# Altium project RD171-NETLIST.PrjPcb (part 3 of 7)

## Sheet 4.SchDoc
size 420 x 297 mm
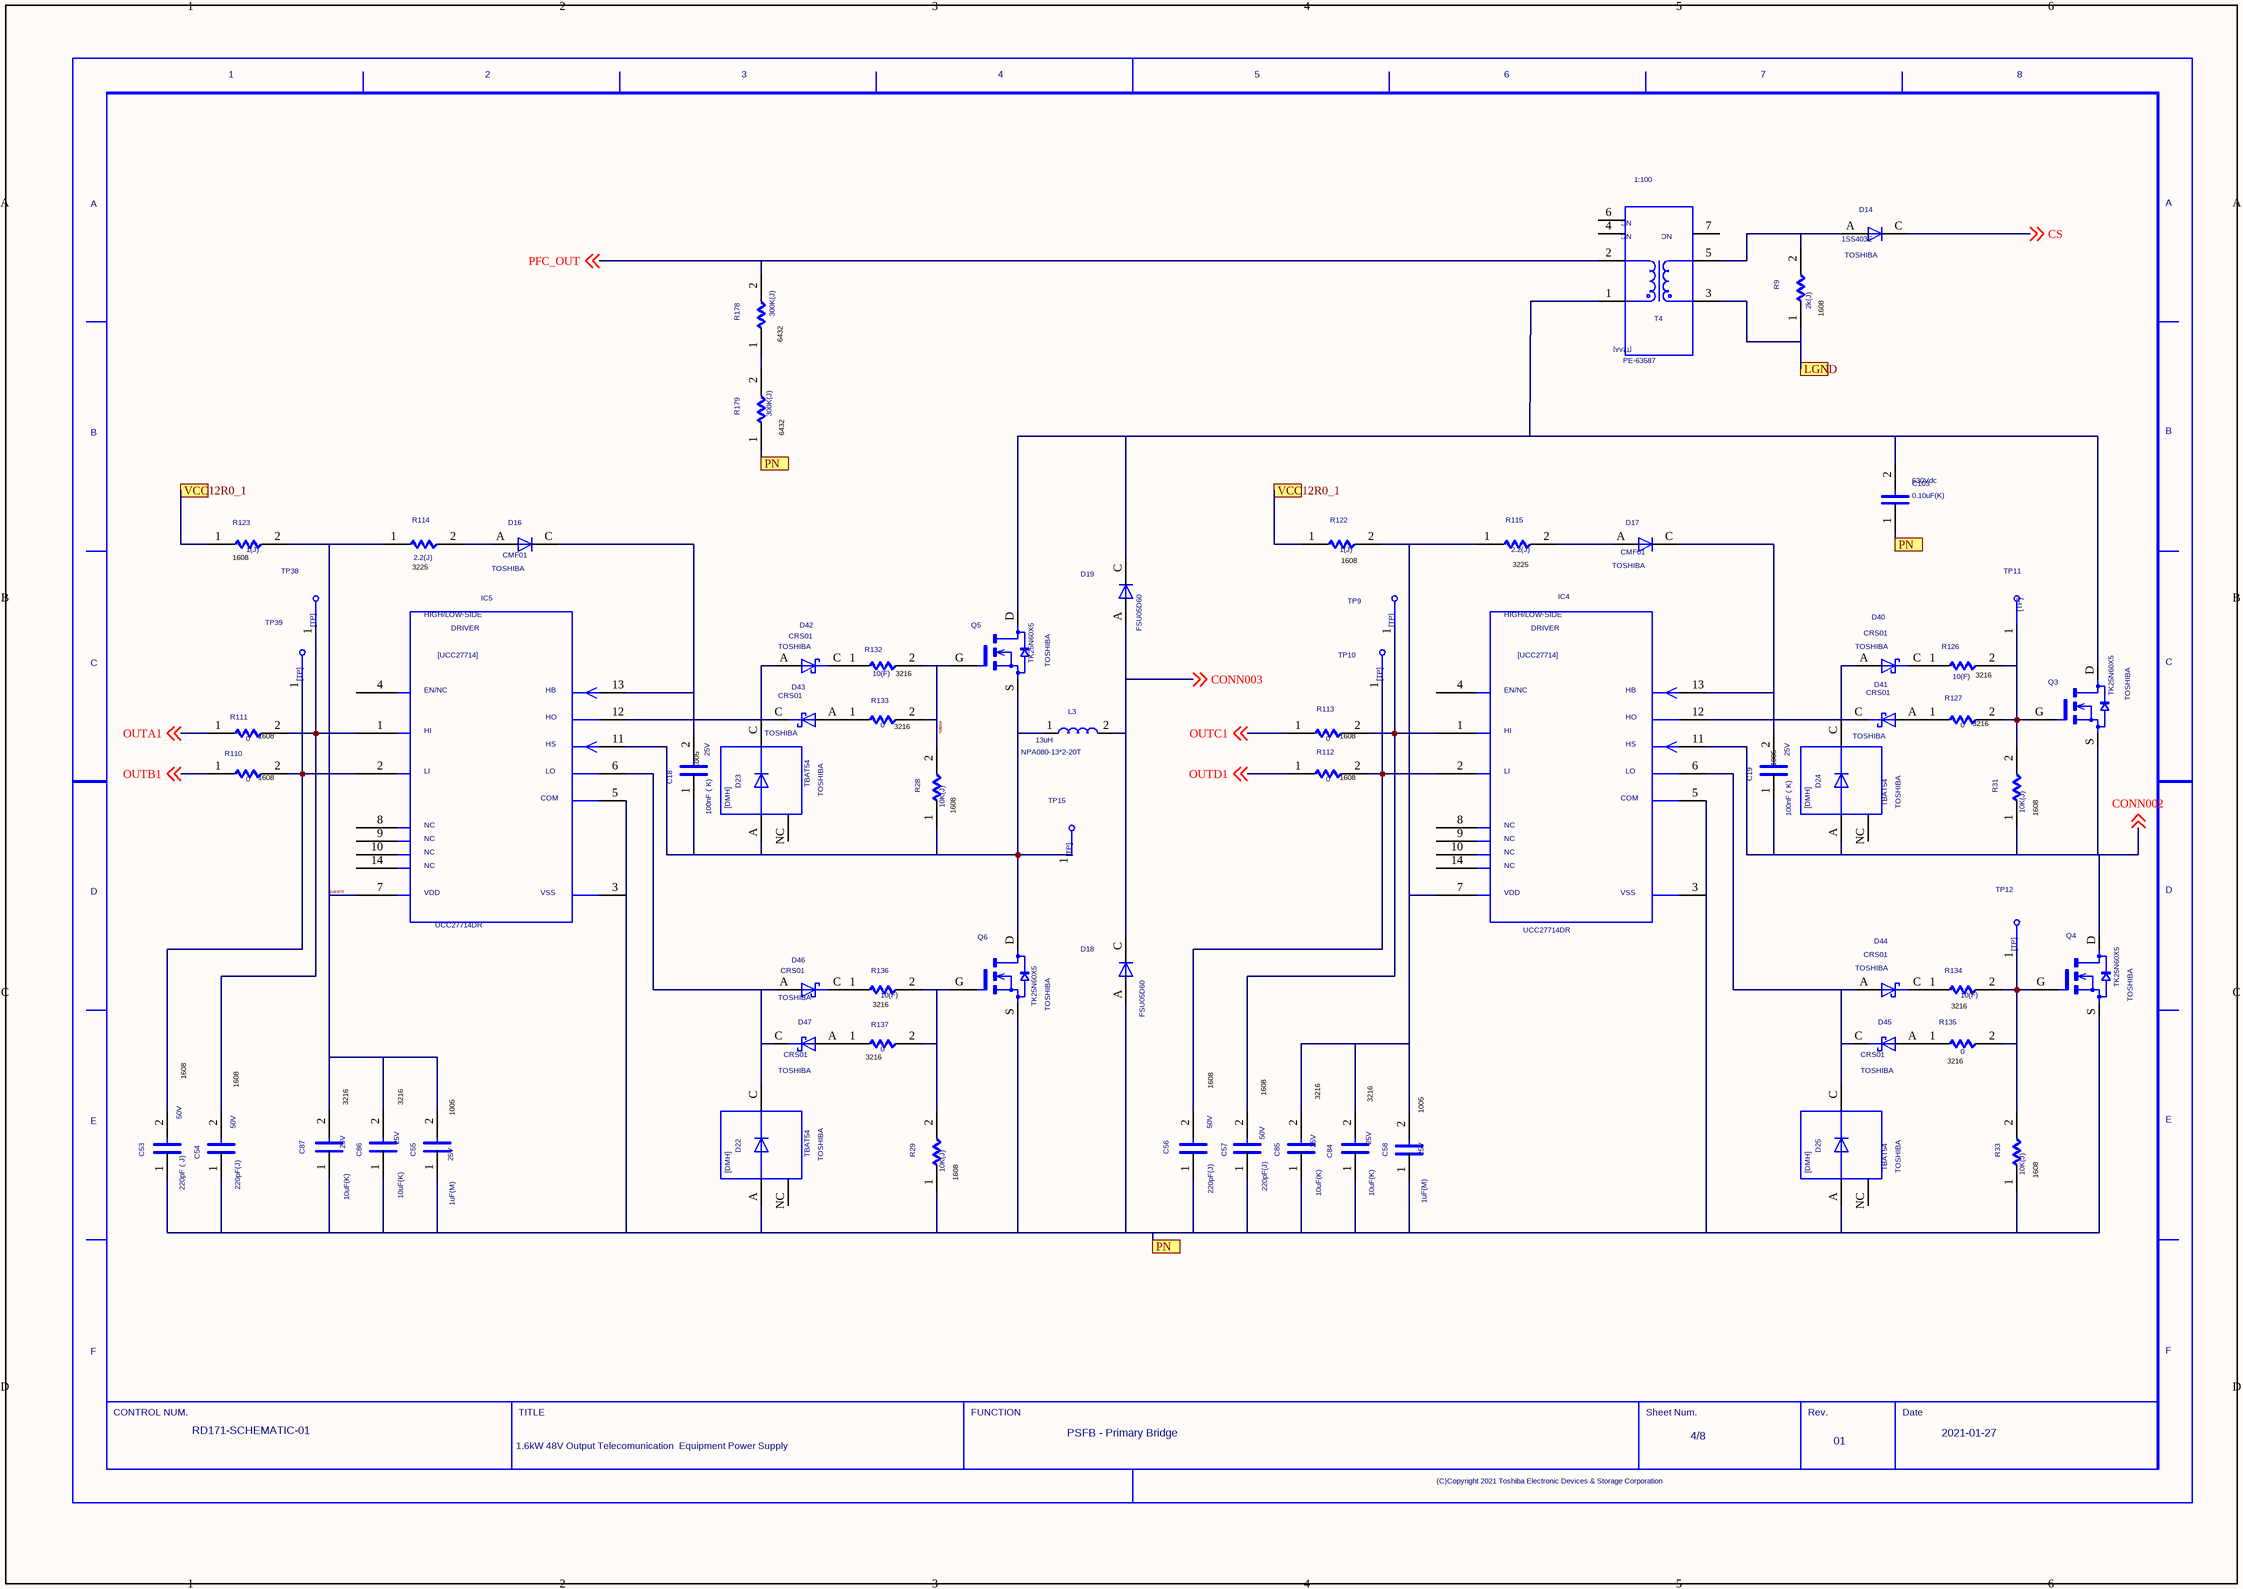
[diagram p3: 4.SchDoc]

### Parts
(Parts that share a designator on the sheet are numbered #1, #2 ... from top to bottom, then left to right.)
C18  VAL2: 25V  VAL1: 100nF（K)  (hidden comment: 100nF)
C19  VAL2: 25V  VAL1: 100nF（K)  (hidden comment: 100nF)
C53  VAL2: 50V  VAL1: 220pF（J)  (hidden comment: 220pF)
C54  VAL2: 50V  VAL1: 220pF(J)  (hidden comment: 220pF)
C55  VAL2: 25V  VAL1: 1uF(M)  (hidden comment: 1uF)
C56  VAL2: 50V  VAL1: 220pF(J)  (hidden comment: 220pF)
C57  VAL2: 50V  VAL1: 220pF(J)  (hidden comment: 220pF)
C58  VAL2: 25V  VAL1: 1uF(M)  (hidden comment: 1uF)
C84  VAL2: 25V  VAL1: 10uF(K)  (hidden comment: 10uF)
C85  VAL2: 25V  VAL1: 10uF(K)  (hidden comment: 10uF)
C86  VAL2: 25V  VAL1: 10uF(K)  (hidden comment: 10uF)
C87  VAL2: 25V  VAL1: 10uF(K)  (hidden comment: 10uF)
C103  VAL1: 0.10uF(K)  VAL2: 630Vdc  (hidden comment: 0.10μF)
D14  USERCOMPTEXT3: TOSHIBA  [1SS403E]  (hidden comment: D14)
D16  USERCOMPTEXT3: TOSHIBA  [CMF01]  (hidden comment: D16)
D17  USERCOMPTEXT3: TOSHIBA  [CMF01]  (hidden comment: D17)
D18  VAL3: FSU05D60  [TRS8E65F]  (hidden comment: D1)
D19  VAL3: FSU05D60  [TRS8E65F]  (hidden comment: D1)
D22  USERCOMPTEXT3: TOSHIBA  [TBAT54]  (hidden comment: D22)
D23  USERCOMPTEXT3: TOSHIBA  [TBAT54]  (hidden comment: D23)
D24  USERCOMPTEXT3: TOSHIBA  [TBAT54]  (hidden comment: D24)
D25  USERCOMPTEXT3: TOSHIBA  [TBAT54]  (hidden comment: D25)
D40  USERCOMPTEXT3: TOSHIBA  [CRS01]  (hidden comment: D40)
D41  USERCOMPTEXT3: TOSHIBA  [CRS01]  (hidden comment: D41)
D42  USERCOMPTEXT3: TOSHIBA  [CRS01]  (hidden comment: D42)
D43  USERCOMPTEXT3: TOSHIBA  [CRS01]  (hidden comment: D43)
D44  USERCOMPTEXT3: TOSHIBA  [CRS01]  (hidden comment: D44)
D45  USERCOMPTEXT3: TOSHIBA  [CRS01]  (hidden comment: D45)
D46  USERCOMPTEXT3: TOSHIBA  [CRS01]  (hidden comment: D46)
D47  USERCOMPTEXT3: TOSHIBA  [CRS01]  (hidden comment: D47)
IC4  IC4  [UCC27714DR]  (value not drawn)
IC5  IC5  [UCC27714DR]  (value not drawn)
L3  VAL3: NPA080-13*2-20T  VAL1: 13uH  [NPA080-14*2-16T]  (hidden comment: 8.4uH)
Q3  USERCOMPTEXT3: TOSHIBA  [TK25N60X5]  (hidden comment: Q3)
Q4  USERCOMPTEXT3: TOSHIBA  [TK25N60X5]  (hidden comment: Q4)
Q5  USERCOMPTEXT3: TOSHIBA  [TK25N60X5]  (hidden comment: Q5)
Q6  USERCOMPTEXT3: TOSHIBA  [TK25N60X5]  (hidden comment: Q6)
R9  VAL1: 2k(J)  (hidden comment: 2k)
R28  VAL1: 10K(J)  (hidden comment: 10k)
R29  VAL1: 10K(J)  (hidden comment: 10k)
R31  VAL1: 10K(J)  (hidden comment: 10k)
R33  VAL1: 10K(J)  (hidden comment: 10k)
R110  0
R111  0
R112  0
R113  0
R114  VAL1: 2.2(J)  (hidden comment: 2.2)
R115  VAL1: 2.2(J)  (hidden comment: 2.2)
R122  VAL1: 1(J)  (hidden comment: 1)
R123  VAL1: 1(J)  (hidden comment: 1)
R126  VAL1: 10(F)  (hidden comment: 10)
R127  0
R132  VAL1: 10(F)  (hidden comment: 10)
R133  0
R134  VAL1: 10(F)  (hidden comment: 10)
R135  0
R136  VAL1: 10(F)  (hidden comment: 10)
R137  0
R178  VAL1: 300K(J)  (hidden comment: 300k)
R179  VAL1: 300K(J)  (hidden comment: 300k)
T4  VAL3: PE-63587  [PE-63587NL]  (hidden comment: 1:100)
TP9  TP9  [HK-2-S]  (value not drawn)
TP10  TP10  [HK-2-S]  (value not drawn)
TP11  TP11  [HK-2-S]  (value not drawn)
TP12  TP12  [HK-2-S]  (value not drawn)
TP15  TP15  [HK-2-S]  (value not drawn)
TP38  TP38  [HK-2-S]  (value not drawn)
TP39  TP39  [HK-2-S]  (value not drawn)
U?#4  DATE: 2021-01-27  REVISION: 01  SHEETNUMBER: 4/8  FUNCTION: PSFB - Primary Bridge  TITLE: 1.6kW 48V Output Telecomunication / Equipment Power Supply  DRAWINGNUMBER: RD171-SCHEMATIC-01  (hidden comment: WAKU_DEF100)

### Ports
LGND, PN, VCC12R0_1

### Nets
CONN002: C19.1 D24.A IC4.11 Q3.S Q4.D R31.1 ; off-sheet CONN002
CONN003: D18.C D19.A L3.2 ; off-sheet CONN003
CS: D14.C ; off-sheet CS
LGND: R9.1 T4.3 ; port LGND
N05004: Q5.G R28.2 R132.2 R133.2
OUTA1: R111.1 ; off-sheet OUTA1
OUTB1: R110.1 ; off-sheet OUTB1
OUTC1: R113.1 ; off-sheet OUTC1
OUTD1: R112.1 ; off-sheet OUTD1
PFC_OUT: R178.2 T4.2 ; off-sheet PFC_OUT
SIG65: C19.2 D17.C IC4.13
SIG75: C18.2 D16.C IC5.13
SIG82: Q6.G R29.2 R136.2 R137.2
SIG89: C54.2 IC5.1 R111.2 TP38.1
SIG90: C53.2 IC5.2 R110.2 TP39.1
SIG91: C58.2 C84.2 C85.2 IC4.7 R115.1 R122.2
SIG92: D17.A R115.2
SIG93: C57.2 IC4.1 R113.2 TP9.1
SIG94: C56.2 IC4.2 R112.2 TP10.1
SIG95: D16.A R114.2
SIG205: Q4.G R33.2 R134.2 R135.2 TP12.1
SIG206: Q3.G R31.2 R126.2 R127.2 TP11.1
SIG249: C18.1 D23.A IC5.11 L3.1 Q5.S Q6.D R28.1 TP15.1
SIGN269: D23.C D42.A D43.C IC5.12
SIGN270: C55.2 C86.2 C87.2 IC5.7 R114.1 R123.2
SIGN271: R178.1 R179.2
SIGN318: D24.C D40.A D41.C IC4.12
SIGN322: D22.C D46.A D47.C IC5.6
SIGN325: D25.C D44.A D45.C IC4.6
SIGN355: C103.2 D19.C Q3.D Q5.D T4.1
SIGN356: D14.A R9.2 T4.5
NetC1_1: C53.1 C54.1 C55.1 C56.1 C57.1 C58.1 C84.1 C85.1 C86.1 C87.1 C103.1 D18.A D22.A D25.A IC4.3 IC4.5 IC5.3 IC5.5 Q4.S Q6.S R29.1 R33.1 R179.1 ; port PN
NetC70_2: R122.1 R123.1 ; port VCC12R0_1
NetD40_C: D40.C R126.1
NetD41_A: D41.A R127.1
NetD42_C: D42.C R132.1
NetD43_A: D43.A R133.1
NetD44_C: D44.C R134.1
NetD45_A: D45.A R135.1
NetD46_C: D46.C R136.1
NetD47_A: D47.A R137.1

Not connected (* = marked no-connect by the designer): D22 NC; D23 NC; D24 NC; D25 NC; IC4 4 8 9 10 14; IC5 4 8 9 10 14; T4 4 6 7

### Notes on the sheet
- (near R9) 1608
- (near R178) 6432
- (near R179) 6432
- (near R123) 1608
- (near R114) 3225
- (near R122) 1608
- (near R115) 3225
- (near R133) 3216
- (near R132) 3216
- (near R127) 3216
- (near R126) 3216
- (near R111) 1608
- (near R110) 1608
- (near C18) 1005
- (near R112) 1608
- (near R113) 1608
- (near C19) 1005
- (near R28) 1608
- (near R31) 1608
- (near R137) 3216
- (near R136) 3216
- (near R135) 3216
- (near R134) 3216
- 1608
- (near C54) 1608
- 3216
- (near C55) 1005
- (near C58) 1005
- (near R29) 1608
- (near R33) 1608

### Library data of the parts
C18 = C: PARTNAME: Chip1005_GS_2; ORIGINALSYMBOLORIGIN: (0,0); TIME: 16:40:04; UPDATEUSER: t5459927; SAVECOUNT: 1; QUADMODEL: CON_220N; FUNCTION: C_C.Normal_package; NOMINALCAPACITA: 220n; RATEDVOLTAGE: 16; CDMASTERCADCELG: KC0005; MAKER: TDK; TEMPCHARACTERI2: B; SIZECODESMD: 1005; OUMEMAKER: TDK ＴＤＫ; ADSCNVFLAG: ON; ADSCOMPONENTNAME: C_1005; COMP: PRT_52; ADSMODELNAME: s_C1005JB1C224KT; FNLEADFREETHET1GT2GMCTH1: N_N_N; VAL3: C1005X7R1E104K050BB; CAPACITANCETOLE: K; OUMECLASSIFICATION: セラミックコンデンサ; OUMEMAKERKATAMEI: C1005JB1C224KT; INSTANCENAME: INS4234
C19 = C: PARTNAME: Chip1005_GS_2; ORIGINALSYMBOLORIGIN: (0,0); TIME: 16:40:04; UPDATEUSER: t5459927; SAVECOUNT: 1; QUADMODEL: CON_220N; FUNCTION: C_C.Normal_package; NOMINALCAPACITA: 220n; RATEDVOLTAGE: 16; CDMASTERCADCELG: KC0005; MAKER: TDK; TEMPCHARACTERI2: B; SIZECODESMD: 1005; OUMEMAKER: TDK ＴＤＫ; COMP: PRT_52; ADSMODELNAME: s_C1005JB1C224KT; FNLEADFREETHET1GT2GMCTH1: N_N_N; VAL3: C1005X7R1E104K050BB; CAPACITANCETOLE: K; OUMECLASSIFICATION: セラミックコンデンサ; OUMEMAKERKATAMEI: C1005JB1C224KT; INSTANCENAME: INS4196
C53 = C: PARTNAME: Chip1608_GS_1; ORIGINALSYMBOLORIGIN: (0,0); TIME: 16:40:04; UPDATEUSER: t5459927; SAVECOUNT: 1; QUADMODEL: CON_220P; FUNCTION: C_C.Normal_package; NOMINALCAPACITA: 220p; RATEDVOLTAGE: 50; CDMASTERCADCELG: KC0008; MAKER: MURATA; SIZECODESMD: 1608; OUMEMAKER: MRT 村田製作所; COMP: PRT_48; ADSMODELNAME: s_GCM1885C1H221JA16D; PMPRODUCTSTYPEG: DME; FNLEADFREETHET1GT2GMCTH1: N_N_N; VAL3: GRM1885C1H221JA01D; CAPACITANCETOLE: J; OUMECLASSIFICATION: セラミックコンデンサ; OUMEMAKERKATAMEI: GCM1885C1H221JA16D; INSTANCENAME: INS4564
C54 = C: PARTNAME: Chip1608_GS_1; ORIGINALSYMBOLORIGIN: (0,0); TIME: 16:40:04; UPDATEUSER: t5459927; SAVECOUNT: 1; QUADMODEL: CON_220P; FUNCTION: C_C.Normal_package; NOMINALCAPACITA: 220p; RATEDVOLTAGE: 50; CDMASTERCADCELG: KC0008; MAKER: MURATA; SIZECODESMD: 1608; OUMEMAKER: MRT 村田製作所; COMP: PRT_48; ADSMODELNAME: s_GCM1885C1H221JA16D; PMPRODUCTSTYPEG: DME; FNLEADFREETHET1GT2GMCTH1: N_N_N; VAL3: GRM1885C1H221JA01D; CAPACITANCETOLE: J; OUMECLASSIFICATION: セラミックコンデンサ; OUMEMAKERKATAMEI: GCM1885C1H221JA16D; INSTANCENAME: INS4576
C55 = C: PARTNAME: Chip1005_GS_2; ORIGINALSYMBOLORIGIN: (0,0); TIME: 16:40:04; UPDATEUSER: t5459927; SAVECOUNT: 1; QUADMODEL: CON_2.2U; FUNCTION: C_C.Normal_package; NOMINALCAPACITA: 2.2u; RATEDVOLTAGE: 10; CDMASTERCADCELG: KC0005; MAKER: TDK; SIZECODESMD: 1005; OUMEMAKER: MRT 村田製作所; ADSCNVFLAG: ON; ADSCOMPONENTNAME: C_1005; COMP: PRT_52; ADSMODELNAME: s_GRM155R61A225KE95D; PMPRODUCTSTYPEG: HD1; FNLEADFREETHET1GT2GMCTH1: N_N_N; VAL3: C1005X5R1E105M050BC; CAPACITANCETOLE: K; OUMECLASSIFICATION: セラミックコンデンサ; OUMEMAKERKATAMEI: GRM155R61A225KE95D; INSTANCENAME: INS4176
C56 = C: PARTNAME: Chip1608_GS_1; ORIGINALSYMBOLORIGIN: (0,0); TIME: 16:40:04; UPDATEUSER: t5459927; SAVECOUNT: 1; QUADMODEL: CON_220P; FUNCTION: C_C.Normal_package; NOMINALCAPACITA: 220p; RATEDVOLTAGE: 50; CDMASTERCADCELG: KC0008; MAKER: MURATA; SIZECODESMD: 1608; OUMEMAKER: MRT 村田製作所; COMP: PRT_48; ADSMODELNAME: s_GCM1885C1H221JA16D; PMPRODUCTSTYPEG: DME; FNLEADFREETHET1GT2GMCTH1: N_N_N; VAL3: GRM1885C1H221JA01D; CAPACITANCETOLE: J; OUMECLASSIFICATION: セラミックコンデンサ; OUMEMAKERKATAMEI: GCM1885C1H221JA16D; INSTANCENAME: INS4452
C57 = C: PARTNAME: Chip1608_GS_1; ORIGINALSYMBOLORIGIN: (0,0); TIME: 16:40:04; UPDATEUSER: t5459927; SAVECOUNT: 1; QUADMODEL: CON_220P; FUNCTION: C_C.Normal_package; NOMINALCAPACITA: 220p; RATEDVOLTAGE: 50; CDMASTERCADCELG: KC0008; MAKER: MURATA; SIZECODESMD: 1608; OUMEMAKER: MRT 村田製作所; COMP: PRT_48; ADSMODELNAME: s_GCM1885C1H221JA16D; PMPRODUCTSTYPEG: DME; FNLEADFREETHET1GT2GMCTH1: N_N_N; VAL3: GRM1885C1H221JA01D; CAPACITANCETOLE: J; OUMECLASSIFICATION: セラミックコンデンサ; OUMEMAKERKATAMEI: GCM1885C1H221JA16D; INSTANCENAME: INS4440
C58 = C: PARTNAME: Chip1005_GS_2; ORIGINALSYMBOLORIGIN: (0,0); TIME: 16:40:04; UPDATEUSER: t5459927; SAVECOUNT: 1; QUADMODEL: CON_2.2U; FUNCTION: C_C.Normal_package; NOMINALCAPACITA: 2.2u; RATEDVOLTAGE: 10; CDMASTERCADCELG: KC0005; MAKER: TDK; SIZECODESMD: 1005; OUMEMAKER: MRT 村田製作所; COMP: PRT_52; ADSMODELNAME: s_GRM155R61A225KE95D; PMPRODUCTSTYPEG: HD1; FNLEADFREETHET1GT2GMCTH1: N_N_N; VAL3: C1005X5R1E105M050BC; CAPACITANCETOLE: K; OUMECLASSIFICATION: セラミックコンデンサ; OUMEMAKERKATAMEI: GRM155R61A225KE95D; INSTANCENAME: INS4186
C84 = C: PARTNAME: Chip3216_GS_1; ORIGINALSYMBOLORIGIN: (0,0); TIME: 16:40:04; UPDATEUSER: t5459927; SAVECOUNT: 1; QUADMODEL: CON_10U; FUNCTION: C_C.Normal_package; NOMINALCAPACITA: 10u; RATEDVOLTAGE: 25; CDMASTERCADCELG: KC0014; MAKER: TAIYO YUDEN; SIZECODESMD: 3216; OUMEMAKER: TYD 太陽誘電; COMP: PRT_46; ADSMODELNAME: s_TMK316LD106KL_T; FNLEADFREETHET1GT2GMCTH1: N_N_N; VAL3: TMK316BJ106KL-T; CAPACITANCETOLE: K; OUMECLASSIFICATION: セラミックコンデンサ; OUMEMAKERKATAMEI: TMK316LD106KL-T; INSTANCENAME: INS4474
C85 = C: PARTNAME: Chip3216_GS_1; ORIGINALSYMBOLORIGIN: (0,0); TIME: 16:40:04; UPDATEUSER: t5459927; SAVECOUNT: 1; QUADMODEL: CON_10U; FUNCTION: C_C.Normal_package; NOMINALCAPACITA: 10u; RATEDVOLTAGE: 25; CDMASTERCADCELG: KC0014; MAKER: TAIYO YUDEN; SIZECODESMD: 3216; OUMEMAKER: TYD 太陽誘電; COMP: PRT_46; ADSMODELNAME: s_TMK316LD106KL_T; FNLEADFREETHET1GT2GMCTH1: N_N_N; VAL3: TMK316BJ106KL-T; CAPACITANCETOLE: K; OUMECLASSIFICATION: セラミックコンデンサ; OUMEMAKERKATAMEI: TMK316LD106KL-T; INSTANCENAME: INS4464
C86 = C: PARTNAME: Chip3216_GS_1; ORIGINALSYMBOLORIGIN: (0,0); TIME: 16:40:04; UPDATEUSER: t5459927; SAVECOUNT: 1; QUADMODEL: CON_10U; FUNCTION: C_C.Normal_package; NOMINALCAPACITA: 10u; RATEDVOLTAGE: 25; CDMASTERCADCELG: KC0014; MAKER: TAIYO YUDEN; SIZECODESMD: 3216; OUMEMAKER: TYD 太陽誘電; COMP: PRT_46; ADSMODELNAME: s_TMK316LD106KL_T; FNLEADFREETHET1GT2GMCTH1: N_N_N; VAL3: TMK316BJ106KL-T; CAPACITANCETOLE: K; OUMECLASSIFICATION: セラミックコンデンサ; OUMEMAKERKATAMEI: TMK316LD106KL-T; INSTANCENAME: INS4598
C87 = C: PARTNAME: Chip3216_GS_1; ORIGINALSYMBOLORIGIN: (0,0); TIME: 16:40:04; UPDATEUSER: t5459927; SAVECOUNT: 1; QUADMODEL: CON_10U; FUNCTION: C_C.Normal_package; NOMINALCAPACITA: 10u; RATEDVOLTAGE: 25; CDMASTERCADCELG: KC0014; MAKER: TAIYO YUDEN; SIZECODESMD: 3216; OUMEMAKER: TYD 太陽誘電; COMP: PRT_46; ADSMODELNAME: s_TMK316LD106KL_T; FNLEADFREETHET1GT2GMCTH1: N_N_N; VAL3: TMK316BJ106KL-T; CAPACITANCETOLE: K; OUMECLASSIFICATION: セラミックコンデンサ; OUMEMAKERKATAMEI: TMK316LD106KL-T; INSTANCENAME: INS4588
C103 = RDER72J104K4K1H03B_0: PARTNAME: RDER72J104_MU; TIME: 16:40:05; UPDATEUSER: t5459927; SAVECOUNT: 1; OriginalSymbolOrigin: (0,0); COMPONENTNAME: RDER72J104K4K1H03B_0_RDER72J104K4K1H03B_0; INSTANCENAME: INS16960092
D14 = D: PARTNAME: 1SS403E_TS_B; UPDATEUSER: t5459927; UPDATETIME: 16:40:05; SAVECOUNT: 1; SAVEAREA0: -225,-91,12804,7836; ORIGINALSYMBOLORIGIN: (0,0); FUNCTION: D_D.Normal_package; CDMASTERCADCELG: D81022; FORWARDVOLTAGEM: 0; OUMEMAKER: TSB 東芝; MOUNTINGFORMSMD: SMD; COMP: PRT_27; ADSMODELNAME: s_1SS352_TPH3_F_1_1E1A; FNLEADFREETHET1GT2GMCTH1: N_N_N; OUMECLASSIFICATION: 小信号ダイオード; MAXREVERSEVOLTA: 80; OUMEMAKERKATAMEI: 1SS352(TPH3,F)1-1E1A; INSTANCENAME: INS4272
D16 = D: PARTNAME: CMF01_TS_B; UPDATEUSER: t5459927; UPDATETIME: 16:40:05; SAVECOUNT: 1; SAVEAREA0: -225,-91,12804,7836; ORIGINALSYMBOLORIGIN: (0,0); FUNCTION: D_D.Normal_package; CDMASTERCADCELG: DD924D; FORWARDVOLTAGEM: 0; MAXAVERAGEFORWA: 2; OUMEMAKER: ONS オンセミコンダクター; MOUNTINGFORMSMD: SMD; COMP: PRT_14; REVERSECURRENT: 50u; ADSMODELNAME: s_MURS220T3G; PMPRODUCTSTYPEG: PJ1; MAXREPETITIVEPE: 200; FNLEADFREETHET1GT2GMCTH1: 3_0_N; OUMECLASSIFICATION: 一般整流素子; OUMEMAKERKATAMEI: MURS220T3G; PEAKFORWARDVOLT: 770m; INSTANCENAME: INS4130
D17 = D: PARTNAME: CMF01_TS_B; UPDATEUSER: t5459927; UPDATETIME: 16:40:05; SAVECOUNT: 1; SAVEAREA0: -225,-91,12804,7836; ORIGINALSYMBOLORIGIN: (0,0); FUNCTION: D_D.Normal_package; CDMASTERCADCELG: DD924D; FORWARDVOLTAGEM: 0; MAXAVERAGEFORWA: 2; OUMEMAKER: ONS オンセミコンダクター; MOUNTINGFORMSMD: SMD; COMP: PRT_14; REVERSECURRENT: 50u; ADSMODELNAME: s_MURS220T3G; PMPRODUCTSTYPEG: PJ1; MAXREPETITIVEPE: 200; FNLEADFREETHET1GT2GMCTH1: 3_0_N; OUMECLASSIFICATION: 一般整流素子; OUMEMAKERKATAMEI: MURS220T3G; PEAKFORWARDVOLT: 770m; INSTANCENAME: INS3988
D18 = D: PARTNAME: FSU05D60_KC; UPDATEUSER: t5459927; UPDATETIME: 16:40:05; SAVECOUNT: 1; SAVEAREA0: -225,-91,12804,7836; ORIGINALSYMBOLORIGIN: (0,0); FUNCTION: D_D.Normal_package; CDMASTERCADCELG: DCR071; MAKER: TOSHIBA; FORWARDVOLTAGEM: 0; USERCOMPTEXT3: KYOCERA; OUMEMAKER: ROH ロー・; MOUNTINGFORMSMD: DIP; COMP: PRT_12; ADSMODELNAME: s_FSU05D60; FNLEADFREETHET1GT2GMCTH1: N_N_N; OUMECLASSIFICATION: 小信号ダイオード; MAXREVERSEVOLTA: 100; INSTANCENAME: INS16993764
D19 = D: PARTNAME: FSU05D60_KC; UPDATEUSER: t5459927; UPDATETIME: 16:40:05; SAVECOUNT: 1; SAVEAREA0: -225,-91,12804,7836; ORIGINALSYMBOLORIGIN: (0,0); FUNCTION: D_D.Normal_package; CDMASTERCADCELG: DCR071; MAKER: TOSHIBA; FORWARDVOLTAGEM: 0; USERCOMPTEXT3: KYOCERA; OUMEMAKER: ROH ロー・; MOUNTINGFORMSMD: DIP; COMP: PRT_12; ADSMODELNAME: s_FSU05D60; FNLEADFREETHET1GT2GMCTH1: N_N_N; OUMECLASSIFICATION: 小信号ダイオード; MAXREVERSEVOLTA: 100; INSTANCENAME: INS16993843
D22 = DMH: PARTNAME: TBAT54_TS_B; UPDATEUSER: t5459927; UPDATETIME: 16:40:05; SAVECOUNT: 1; SAVEAREA0: -4931,-287,27399,20979; ORIGINALSYMBOLORIGIN: (0,0); COMPONENTNAME: DMH_DMH.Normal_package; COMP: PRT_25; INSTANCENAME: INS4258
D23 = DMH: PARTNAME: TBAT54_TS_B; UPDATEUSER: t5459927; UPDATETIME: 16:40:05; SAVECOUNT: 1; SAVEAREA0: -4931,-287,27399,20979; ORIGINALSYMBOLORIGIN: (0,0); COMPONENTNAME: DMH_DMH.Normal_package; COMP: PRT_25; INSTANCENAME: INS4244
D24 = DMH: PARTNAME: TBAT54_TS_B; UPDATEUSER: t5459927; UPDATETIME: 16:40:05; SAVECOUNT: 1; SAVEAREA0: -4931,-287,27399,20979; ORIGINALSYMBOLORIGIN: (0,0); COMPONENTNAME: DMH_DMH.Normal_package; COMP: PRT_25; INSTANCENAME: INS4220
D25 = DMH: PARTNAME: TBAT54_TS_B; UPDATEUSER: t5459927; UPDATETIME: 16:40:05; SAVECOUNT: 1; SAVEAREA0: -4931,-287,27399,20979; ORIGINALSYMBOLORIGIN: (0,0); COMPONENTNAME: DMH_DMH.Normal_package; COMP: PRT_25; INSTANCENAME: INS4206
D40 = SBD: PARTNAME: CRS01_TS_B; UPDATEUSER: t5459927; UPDATETIME: 16:40:05; SAVECOUNT: 1; SAVEAREA0: -4630,-153,17114,13055; ORIGINALSYMBOLORIGIN: (0,0); COMPONENTNAME: SBD_SBD.Normal_package; COMP: PRT_11; INSTANCENAME: INS4304
D41 = SBD: PARTNAME: CRS01_TS_B; UPDATEUSER: t5459927; UPDATETIME: 16:40:05; SAVECOUNT: 1; SAVEAREA0: -4630,-153,17114,13055; ORIGINALSYMBOLORIGIN: (0,0); COMPONENTNAME: SBD_SBD.Normal_package; COMP: PRT_11; INSTANCENAME: INS4316
D42 = SBD: PARTNAME: CRS01_TS_B; UPDATEUSER: t5459927; UPDATETIME: 16:40:05; SAVECOUNT: 1; SAVEAREA0: -4630,-153,17114,13055; ORIGINALSYMBOLORIGIN: (0,0); COMPONENTNAME: SBD_SBD.Normal_package; COMP: PRT_11; INSTANCENAME: INS4348
D43 = SBD: PARTNAME: CRS01_TS_B; UPDATEUSER: t5459927; UPDATETIME: 16:40:05; SAVECOUNT: 1; SAVEAREA0: -4630,-153,17114,13055; ORIGINALSYMBOLORIGIN: (0,0); COMPONENTNAME: SBD_SBD.Normal_package; COMP: PRT_11; INSTANCENAME: INS4360
D44 = SBD: PARTNAME: CRS01_TS_B; UPDATEUSER: t5459927; UPDATETIME: 16:40:05; SAVECOUNT: 1; SAVEAREA0: -4630,-153,17114,13055; ORIGINALSYMBOLORIGIN: (0,0); COMPONENTNAME: SBD_SBD.Normal_package; COMP: PRT_11; INSTANCENAME: INS4326
D45 = SBD: PARTNAME: CRS01_TS_B; UPDATEUSER: t5459927; UPDATETIME: 16:40:05; SAVECOUNT: 1; SAVEAREA0: -4630,-153,17114,13055; ORIGINALSYMBOLORIGIN: (0,0); COMPONENTNAME: SBD_SBD.Normal_package; COMP: PRT_11; INSTANCENAME: INS4338
D46 = SBD: PARTNAME: CRS01_TS_B; UPDATEUSER: t5459927; UPDATETIME: 16:40:05; SAVECOUNT: 1; SAVEAREA0: -4630,-153,17114,13055; ORIGINALSYMBOLORIGIN: (0,0); COMPONENTNAME: SBD_SBD.Normal_package; COMP: PRT_11; INSTANCENAME: INS4370
D47 = SBD: PARTNAME: CRS01_TS_B; UPDATEUSER: t5459927; UPDATETIME: 16:40:05; SAVECOUNT: 1; SAVEAREA0: -4630,-153,17114,13055; ORIGINALSYMBOLORIGIN: (0,0); COMPONENTNAME: SBD_SBD.Normal_package; COMP: PRT_11; INSTANCENAME: INS4382
IC4 = L27714: PARTNAME: UCC27714D_TI; UPDATEUSER: t5459927; UPDATETIME: 16:40:04; SAVECOUNT: 1; SAVEAREA0: -43740,-59600,92622,3258; ORIGINALSYMBOLORIGIN: (7620,0); COMP: PRT_58; FUNCTION: L27714_L27714.Normal_package; MAKER: TEXAS; INSTANCENAME: INS3954
IC5 = L27714: PARTNAME: UCC27714D_TI; UPDATEUSER: t5459927; UPDATETIME: 16:40:04; SAVECOUNT: 1; SAVEAREA0: -43740,-59600,92622,3258; ORIGINALSYMBOLORIGIN: (7620,0); COMP: PRT_58; FUNCTION: L27714_L27714.Normal_package; MAKER: TEXAS; INSTANCENAME: INS4072
L3 = L: PARTNAME: NPA080-13x2-20T_GS; ORIGINALSYMBOLORIGIN: (0,0); TIME: 16:40:05; UPDATEUSER: t5459927; SAVECOUNT: 1; COMPONENTNAME: L_L.Normal_package; INDUCTANCEMIN: 0; MOUNTINGFORMSMD: DIP; MAKER: FURUKAWA; VAL2: (Rated Current/Idc=0A); NOMINALINDUCTA2: K; NOMINALINDUCTA1: 8.4u; COMP: PRT_41; INSTANCENAME: INS16989329
Q3 = MFNF_3: PARTNAME: TK25N60X5_TS; SAVEAREA0: -7027,-292,21786,15988; ORIGINALSYMBOLORIGIN: (0,0); SAVECOUNT: 1; TIME: 16:40:05; UPDATEUSER: t5459927; COMPONENTNAME: MFNF_3_MFNF_3; COMP: PRT_9; INSTANCENAME: INS4010
Q4 = MFNF_3: PARTNAME: TK25N60X5_TS; SAVEAREA0: -7027,-292,21786,15988; ORIGINALSYMBOLORIGIN: (0,0); SAVECOUNT: 1; TIME: 16:40:05; UPDATEUSER: t5459927; COMPONENTNAME: MFNF_3_MFNF_3; COMP: PRT_9; INSTANCENAME: INS4034
Q5 = MFNF_3: PARTNAME: TK25N60X5_TS; SAVEAREA0: -7027,-292,21786,15988; ORIGINALSYMBOLORIGIN: (0,0); SAVECOUNT: 1; TIME: 16:40:05; UPDATEUSER: t5459927; COMPONENTNAME: MFNF_3_MFNF_3; COMP: PRT_9; INSTANCENAME: INS4116
Q6 = MFNF_3: PARTNAME: TK25N60X5_TS; SAVEAREA0: -7027,-292,21786,15988; ORIGINALSYMBOLORIGIN: (0,0); SAVECOUNT: 1; TIME: 16:40:05; UPDATEUSER: t5459927; COMPONENTNAME: MFNF_3_MFNF_3; COMP: PRT_9; INSTANCENAME: INS4152
R9 = R: PARTNAME: Chip1608_GS_1; ORIGINALSYMBOLORIGIN: (0,0); TIME: 16:40:04; UPDATEUSER: t5459927; SAVECOUNT: 1; QUADMODEL: RES_4.87K; FUNCTION: R_R.Normal_package; CDMASTERCADCELG: DR901A; MAKER: KOA; RESISTANCETOLER: F; SIZECODESMD: 3216; OUMEMAKER: KOA コーア; ADSCNVFLAG: ON; POWERRATING: 250m; MOUNTINGFORMSMD: SMD; ADSCOMPONENTNAME: R_3216; NOMINALRESISTAN: 4.87K; COMP: PRT_8; ADSMODELNAME: s_RK73H2BTTD4871F; FNLEADFREETHET1GT2GMCTH1: 3_1_N; VAL3: RK73B1JTTD202J; VAL2: 100mW,±5%; OUMECLASSIFICATION: 表面実装用固定抵抗器; OUMEMAKERKATAMEI: RK73H2BTTD4871F; CHIPSIZE: 1608; INSTANCENAME: INS4166
R28 = R: PARTNAME: Chip1608_GS_1; ORIGINALSYMBOLORIGIN: (0,0); TIME: 16:40:04; UPDATEUSER: t5459927; SAVECOUNT: 1; QUADMODEL: RES_10K; FUNCTION: R_R.Normal_package; CDMASTERCADCELG: KC0133; MAKER: KOA; RESISTANCETOLER: J; SIZECODESMD: 1608; OUMEMAKER: KOA コーア; POWERRATING: 100m; MOUNTINGFORMSMD: SMD; COMP: PRT_8; ADSMODELNAME: s_RK73B1JTTD103J@@; FNLEADFREETHET1GT2GMCTH1: N_N_N; VAL3: RK73B1JTTD103J; VAL2: 100mW,±5%; OUMECLASSIFICATION: 表面実装用固定抵抗器; OUMEMAKERKATAMEI: RK73B1JTTD103J@@; INSTANCENAME: INS4106
R29 = R: PARTNAME: Chip1608_GS_1; ORIGINALSYMBOLORIGIN: (0,0); TIME: 16:40:04; UPDATEUSER: t5459927; SAVECOUNT: 1; QUADMODEL: RES_10K; FUNCTION: R_R.Normal_package; CDMASTERCADCELG: KC0133; MAKER: KOA; RESISTANCETOLER: J; SIZECODESMD: 1608; OUMEMAKER: KOA コーア; POWERRATING: 100m; MOUNTINGFORMSMD: SMD; COMP: PRT_8; ADSMODELNAME: s_RK73B1JTTD103J@@; FNLEADFREETHET1GT2GMCTH1: N_N_N; VAL3: RK73B1JTTD103J; VAL2: 100mW,±5%; OUMECLASSIFICATION: 表面実装用固定抵抗器; OUMEMAKERKATAMEI: RK73B1JTTD103J@@; INSTANCENAME: INS4142
R31 = R: PARTNAME: Chip1608_GS_1; ORIGINALSYMBOLORIGIN: (0,0); TIME: 16:40:04; UPDATEUSER: t5459927; SAVECOUNT: 1; QUADMODEL: RES_10K; FUNCTION: R_R.Normal_package; CDMASTERCADCELG: KC0133; MAKER: KOA; RESISTANCETOLER: J; SIZECODESMD: 1608; OUMEMAKER: KOA コーア; POWERRATING: 100m; MOUNTINGFORMSMD: SMD; COMP: PRT_8; ADSMODELNAME: s_RK73B1JTTD103J@@; FNLEADFREETHET1GT2GMCTH1: N_N_N; VAL3: RK73B1JTTD103J; VAL2: 100mW,±5%; OUMECLASSIFICATION: 表面実装用固定抵抗器; OUMEMAKERKATAMEI: RK73B1JTTD103J@@; INSTANCENAME: INS4000
R33 = R: PARTNAME: Chip1608_GS_1; ORIGINALSYMBOLORIGIN: (0,0); TIME: 16:40:04; UPDATEUSER: t5459927; SAVECOUNT: 1; QUADMODEL: RES_10K; FUNCTION: R_R.Normal_package; CDMASTERCADCELG: KC0133; MAKER: KOA; RESISTANCETOLER: J; SIZECODESMD: 1608; OUMEMAKER: KOA コーア; POWERRATING: 100m; MOUNTINGFORMSMD: SMD; COMP: PRT_8; ADSMODELNAME: s_RK73B1JTTD103J@@; FNLEADFREETHET1GT2GMCTH1: N_N_N; VAL3: RK73B1JTTD103J; VAL2: 100mW,±5%; OUMECLASSIFICATION: 表面実装用固定抵抗器; OUMEMAKERKATAMEI: RK73B1JTTD103J@@; INSTANCENAME: INS4024
R110 = R: PARTNAME: Chip1608_GS_1; ORIGINALSYMBOLORIGIN: (0,0); TIME: 16:40:04; UPDATEUSER: t5459927; SAVECOUNT: 1; QUADMODEL: RES_0; FUNCTION: R_R.Normal_package; CDMASTERCADCELG: KCK0203; MAKER: KOA; RESISTANCETOLER: X; SIZECODESMD: 1608; OUMEMAKER: KOA コーア; POWERRATING: 100m; MOUNTINGFORMSMD: SMD; COMP: PRT_8; ADSMODELNAME: s_RK73Z1JTTD; PMPRODUCTSTYPEG: DME-HD1-PC1; FNLEADFREETHET1GT2GMCTH1: 3_2_N; VAL3: RK73Z1JTTD; VAL2: 100mW; OUMECLASSIFICATION: 表面実装用固定抵抗器; INSTANCENAME: INS4534
R111 = R: PARTNAME: Chip1608_GS_1; ORIGINALSYMBOLORIGIN: (0,0); TIME: 16:40:04; UPDATEUSER: t5459927; SAVECOUNT: 1; QUADMODEL: RES_0; FUNCTION: R_R.Normal_package; CDMASTERCADCELG: KCK0203; MAKER: KOA; RESISTANCETOLER: X; SIZECODESMD: 1608; OUMEMAKER: KOA コーア; POWERRATING: 100m; MOUNTINGFORMSMD: SMD; COMP: PRT_8; ADSMODELNAME: s_RK73Z1JTTD; PMPRODUCTSTYPEG: DME-HD1-PC1; FNLEADFREETHET1GT2GMCTH1: 3_2_N; VAL3: RK73Z1JTTD; VAL2: 100mW; OUMECLASSIFICATION: 表面実装用固定抵抗器; INSTANCENAME: INS4544
R112 = R: PARTNAME: Chip1608_GS_1; ORIGINALSYMBOLORIGIN: (0,0); TIME: 16:40:04; UPDATEUSER: t5459927; SAVECOUNT: 1; QUADMODEL: RES_0; FUNCTION: R_R.Normal_package; CDMASTERCADCELG: KCK0203; MAKER: KOA; RESISTANCETOLER: X; SIZECODESMD: 1608; OUMEMAKER: KOA コーア; POWERRATING: 100m; MOUNTINGFORMSMD: SMD; COMP: PRT_8; ADSMODELNAME: s_RK73Z1JTTD; PMPRODUCTSTYPEG: DME-HD1-PC1; FNLEADFREETHET1GT2GMCTH1: 3_2_N; VAL3: RK73Z1JTTD; VAL2: 100mW; OUMECLASSIFICATION: 表面実装用固定抵抗器; INSTANCENAME: INS4430
R113 = R: PARTNAME: Chip1608_GS_1; ORIGINALSYMBOLORIGIN: (0,0); TIME: 16:40:04; UPDATEUSER: t5459927; SAVECOUNT: 1; QUADMODEL: RES_0; FUNCTION: R_R.Normal_package; CDMASTERCADCELG: KCK0203; MAKER: KOA; RESISTANCETOLER: X; SIZECODESMD: 1608; OUMEMAKER: KOA コーア; POWERRATING: 100m; MOUNTINGFORMSMD: SMD; COMP: PRT_8; ADSMODELNAME: s_RK73Z1JTTD; PMPRODUCTSTYPEG: DME-HD1-PC1; FNLEADFREETHET1GT2GMCTH1: 3_2_N; VAL3: RK73Z1JTTD; VAL2: 100mW; OUMECLASSIFICATION: 表面実装用固定抵抗器; INSTANCENAME: INS4420
R114 = R: PARTNAME: Chip3225_GS_1; ORIGINALSYMBOLORIGIN: (0,0); TIME: 16:40:04; UPDATEUSER: t5459927; SAVECOUNT: 1; QUADMODEL: RES_2.2; FUNCTION: R_R.Normal_package; CDMASTERCADCELG: DR903A; MAKER: PANASONIC; RESISTANCETOLER: J; SIZECODESMD: 3225; OUMEMAKER: KOA コーア; POWERRATING: 500m; MOUNTINGFORMSMD: SMD; COMP: PRT_23; ADSMODELNAME: s_RK73B2ETTD2R2J; FNLEADFREETHET1GT2GMCTH1: N_N_N; VAL3: ERJ-14YJ2R2U; VAL2: 500mW,±5%; OUMECLASSIFICATION: 表面実装用固定抵抗器; OUMEMAKERKATAMEI: RK73B2ETTD2R2J; INSTANCENAME: INS4554
R115 = R: PARTNAME: Chip3225_GS_1; ORIGINALSYMBOLORIGIN: (0,0); TIME: 16:40:04; UPDATEUSER: t5459927; SAVECOUNT: 1; QUADMODEL: RES_2.2; FUNCTION: R_R.Normal_package; CDMASTERCADCELG: KC0013; MAKER: PANASONIC; RESISTANCETOLER: J; SIZECODESMD: 3225; OUMEMAKER: KOA コーア; POWERRATING: 500m; MOUNTINGFORMSMD: SMD; COMP: PRT_23; ADSMODELNAME: s_SG73P2ETTD2R2J; PMPRODUCTSTYPEG: SV1; FNLEADFREETHET1GT2GMCTH1: 3_0_N; VAL3: ERJ-14YJ2R2U; VAL2: 500mW,±5%; OUMECLASSIFICATION: 表面実装用固定抵抗器; OUMEMAKERKATAMEI: SG73P2ETTD2R2J; INSTANCENAME: INS4410
R122 = R: PARTNAME: Chip1608_GS_1; ORIGINALSYMBOLORIGIN: (0,0); TIME: 16:40:04; UPDATEUSER: t5459927; QUADMODEL: RES_1; FUNCTION: R_R.Normal_package; CDMASTERCADCELG: KC0165; MAKER: PANASONIC; RESISTANCETOLER: J; SIZECODESMD: 1608; OUMEMAKER: NAE パナソニックエレクトロニックデバイス; POWERRATING: 100m; MOUNTINGFORMSMD: SMD; COMP: PRT_8; ADSMODELNAME: s_ERJ3RQJ1R0V@@; PMPRODUCTSTYPEG: DA; FNLEADFREETHET1GT2GMCTH1: N_N_N; VAL3: ERJ-3GEYJ1R0V; VAL2: 100mW,±5%; OUMECLASSIFICATION: 表面実装用固定抵抗器; OUMEMAKERKATAMEI: ERJ3RQJ1R0V@@; INSTANCENAME: INS4400
R123 = R: PARTNAME: Chip1608_GS_1; ORIGINALSYMBOLORIGIN: (0,0); TIME: 16:40:04; UPDATEUSER: t5459927; QUADMODEL: RES_1; FUNCTION: R_R.Normal_package; CDMASTERCADCELG: KC0165; MAKER: PANASONIC; RESISTANCETOLER: J; SIZECODESMD: 1608; OUMEMAKER: NAE パナソニックエレクトロニックデバイス; POWERRATING: 100m; MOUNTINGFORMSMD: SMD; COMP: PRT_8; ADSMODELNAME: s_ERJ3RQJ1R0V@@; PMPRODUCTSTYPEG: DA; FNLEADFREETHET1GT2GMCTH1: N_N_N; VAL3: ERJ-3GEYJ1R0V; VAL2: 100mW,±5%; OUMECLASSIFICATION: 表面実装用固定抵抗器; OUMEMAKERKATAMEI: ERJ3RQJ1R0V@@; INSTANCENAME: INS4524
R126 = R: PARTNAME: Chip3216_GS_1; ORIGINALSYMBOLORIGIN: (0,0); TIME: 16:40:04; UPDATEUSER: t5459927; SAVECOUNT: 1; QUADMODEL: RES_1M; FUNCTION: R_R.Normal_package; CDMASTERCADCELG: KC0020; MAKER: KOA; RESISTANCETOLER: J; SIZECODESMD: 3216; OUMEMAKER: SSM 進工業; POWERRATING: 500m; MOUNTINGFORMSMD: SMD; NOMINALRESISTAN: 1m; COMP: PRT_5; ADSMODELNAME: s_RL1632H_R001_JN; FNLEADFREETHET1GT2GMCTH1: N_N_N; VAL3: RK73Z2BTTD; VAL2: 500mW; OUMECLASSIFICATION: 表面実装用固定抵抗器; OUMEMAKERKATAMEI: RL1632H-R001-JN; INSTANCENAME: INS4484
R127 = R: PARTNAME: Chip3216_GS_1; ORIGINALSYMBOLORIGIN: (0,0); TIME: 16:40:04; UPDATEUSER: t5459927; SAVECOUNT: 1; QUADMODEL: RES_1M; FUNCTION: R_R.Normal_package; CDMASTERCADCELG: KC0020; MAKER: KOA; RESISTANCETOLER: J; SIZECODESMD: 3216; OUMEMAKER: SSM 進工業; POWERRATING: 500m; MOUNTINGFORMSMD: SMD; NOMINALRESISTAN: 1m; COMP: PRT_5; ADSMODELNAME: s_RL1632H_R001_JN; FNLEADFREETHET1GT2GMCTH1: N_N_N; VAL3: RK73Z2BTTD; VAL2: 500mW; OUMECLASSIFICATION: 表面実装用固定抵抗器; OUMEMAKERKATAMEI: RL1632H-R001-JN; INSTANCENAME: INS4494
R132 = R: PARTNAME: Chip3216_GS_1; ORIGINALSYMBOLORIGIN: (0,0); TIME: 16:40:04; UPDATEUSER: t5459927; SAVECOUNT: 1; QUADMODEL: RES_1M; FUNCTION: R_R.Normal_package; CDMASTERCADCELG: KC0020; MAKER: KOA; RESISTANCETOLER: J; SIZECODESMD: 3216; OUMEMAKER: SSM 進工業; POWERRATING: 500m; MOUNTINGFORMSMD: SMD; NOMINALRESISTAN: 1m; COMP: PRT_5; ADSMODELNAME: s_RL1632H_R001_JN; FNLEADFREETHET1GT2GMCTH1: N_N_N; VAL3: RK73Z2BTTD; VAL2: 500mW; OUMECLASSIFICATION: 表面実装用固定抵抗器; OUMEMAKERKATAMEI: RL1632H-R001-JN; INSTANCENAME: INS4608
R133 = R: PARTNAME: Chip3216_GS_1; ORIGINALSYMBOLORIGIN: (0,0); TIME: 16:40:04; UPDATEUSER: t5459927; SAVECOUNT: 1; QUADMODEL: RES_1M; FUNCTION: R_R.Normal_package; CDMASTERCADCELG: KC0020; MAKER: KOA; RESISTANCETOLER: J; SIZECODESMD: 3216; OUMEMAKER: SSM 進工業; POWERRATING: 500m; MOUNTINGFORMSMD: SMD; NOMINALRESISTAN: 1m; COMP: PRT_5; ADSMODELNAME: s_RL1632H_R001_JN; FNLEADFREETHET1GT2GMCTH1: N_N_N; VAL3: RK73Z2BTTD; VAL2: 500mW; OUMECLASSIFICATION: 表面実装用固定抵抗器; OUMEMAKERKATAMEI: RL1632H-R001-JN; INSTANCENAME: INS4618
R134 = R: PARTNAME: Chip3216_GS_1; ORIGINALSYMBOLORIGIN: (0,0); TIME: 16:40:04; UPDATEUSER: t5459927; SAVECOUNT: 1; QUADMODEL: RES_1M; FUNCTION: R_R.Normal_package; CDMASTERCADCELG: KC0020; MAKER: KOA; RESISTANCETOLER: J; SIZECODESMD: 3216; OUMEMAKER: SSM 進工業; POWERRATING: 500m; MOUNTINGFORMSMD: SMD; NOMINALRESISTAN: 1m; COMP: PRT_5; ADSMODELNAME: s_RL1632H_R001_JN; FNLEADFREETHET1GT2GMCTH1: N_N_N; VAL3: RK73Z2BTTD; VAL2: 500mW; OUMECLASSIFICATION: 表面実装用固定抵抗器; OUMEMAKERKATAMEI: RL1632H-R001-JN; INSTANCENAME: INS4504
R135 = R: PARTNAME: Chip3216_GS_1; ORIGINALSYMBOLORIGIN: (0,0); TIME: 16:40:04; UPDATEUSER: t5459927; SAVECOUNT: 1; QUADMODEL: RES_1M; FUNCTION: R_R.Normal_package; CDMASTERCADCELG: KC0020; MAKER: KOA; RESISTANCETOLER: J; SIZECODESMD: 3216; OUMEMAKER: SSM 進工業; POWERRATING: 500m; MOUNTINGFORMSMD: SMD; NOMINALRESISTAN: 1m; COMP: PRT_5; ADSMODELNAME: s_RL1632H_R001_JN; FNLEADFREETHET1GT2GMCTH1: N_N_N; VAL3: RK73Z2BTTD; VAL2: 500mW; OUMECLASSIFICATION: 表面実装用固定抵抗器; OUMEMAKERKATAMEI: RL1632H-R001-JN; INSTANCENAME: INS4514
R136 = R: PARTNAME: Chip3216_GS_1; ORIGINALSYMBOLORIGIN: (0,0); TIME: 16:40:04; UPDATEUSER: t5459927; SAVECOUNT: 1; QUADMODEL: RES_1M; FUNCTION: R_R.Normal_package; CDMASTERCADCELG: KC0020; MAKER: KOA; RESISTANCETOLER: J; SIZECODESMD: 3216; OUMEMAKER: SSM 進工業; POWERRATING: 500m; MOUNTINGFORMSMD: SMD; NOMINALRESISTAN: 1m; COMP: PRT_5; ADSMODELNAME: s_RL1632H_R001_JN; FNLEADFREETHET1GT2GMCTH1: N_N_N; VAL3: RK73Z2BTTD; VAL2: 500mW; OUMECLASSIFICATION: 表面実装用固定抵抗器; OUMEMAKERKATAMEI: RL1632H-R001-JN; INSTANCENAME: INS4628
R137 = R: PARTNAME: Chip3216_GS_1; ORIGINALSYMBOLORIGIN: (0,0); TIME: 16:40:04; UPDATEUSER: t5459927; SAVECOUNT: 1; QUADMODEL: RES_1M; FUNCTION: R_R.Normal_package; CDMASTERCADCELG: KC0020; MAKER: KOA; RESISTANCETOLER: J; SIZECODESMD: 3216; OUMEMAKER: SSM 進工業; POWERRATING: 500m; MOUNTINGFORMSMD: SMD; NOMINALRESISTAN: 1m; COMP: PRT_5; ADSMODELNAME: s_RL1632H_R001_JN; FNLEADFREETHET1GT2GMCTH1: N_N_N; VAL3: RK73Z2BTTD; VAL2: 500mW; OUMECLASSIFICATION: 表面実装用固定抵抗器; OUMEMAKERKATAMEI: RL1632H-R001-JN; INSTANCENAME: INS4638
R178 = R: PARTNAME: Chip6432_GS; ORIGINALSYMBOLORIGIN: (0,0); TIME: 16:40:04; UPDATEUSER: t5459927; SAVECOUNT: 1; COMP: PRT_43; CHIPSIZE: 6432; FUNCTION: R_R.Normal_package; VAL3: CRCW2512300KJNEG; VAL2: 1W,±5%; MAKER: VISHAY; INSTANCENAME: INS4284
R179 = R: PARTNAME: Chip6432_GS; ORIGINALSYMBOLORIGIN: (0,0); TIME: 16:40:04; UPDATEUSER: t5459927; SAVECOUNT: 1; COMP: PRT_43; CHIPSIZE: 6432; FUNCTION: R_R.Normal_package; VAL3: CRCW2512300KJNEG; VAL2: 1W,±5%; MAKER: VISHAY; INSTANCENAME: INS4294
T4 = T2AA: PARTNAME: PE-63587NL_PU; UPDATEUSER: t5459927; UPDATETIME: 16:40:04; SAVECOUNT: 1; SAVEAREA0: -20981,-344,43891,33349; ORIGINALSYMBOLORIGIN: (0,0); COMPONENTNAME: T2AA_T2AA.Normal_package; INDUCTANCEMIN: 0; MOUNTINGFORMSMD: DIP; MAKER: PULSE; NOMINALINDUCTA2: X; NOMINALINDUCTA1: 140u; COMP: PRT_65; INSTANCENAME: INS4720
TP9 = TP: PARTNAME: HK-2_M8; UPDATEUSER: t5459927; UPDATETIME: 16:40:05; SAVECOUNT: 1; SAVEAREA0: -242,-92,12810,7836; ORIGINALSYMBOLORIGIN: (0,0); COMPONENTNAME: TP_TP.Normal_package; ID: OUTC1; MAKER: MAC8; COMP: PRT_44; INSTANCENAME: INS4648
TP10 = TP: PARTNAME: HK-2_M8; UPDATEUSER: t5459927; UPDATETIME: 16:40:05; SAVECOUNT: 1; SAVEAREA0: -242,-92,12810,7836; ORIGINALSYMBOLORIGIN: (0,0); COMPONENTNAME: TP_TP.Normal_package; ID: OUTD1; MAKER: MAC8; COMP: PRT_44; INSTANCENAME: INS4656
TP11 = TP: PARTNAME: HK-2_M8; UPDATEUSER: t5459927; UPDATETIME: 16:40:05; SAVECOUNT: 1; SAVEAREA0: -242,-92,12810,7836; ORIGINALSYMBOLORIGIN: (0,0); COMPONENTNAME: TP_TP.Normal_package; ID: Q3-G; MAKER: MAC8; COMP: PRT_44; INSTANCENAME: INS4664
TP12 = TP: PARTNAME: HK-2_M8; UPDATEUSER: t5459927; UPDATETIME: 16:40:05; SAVECOUNT: 1; SAVEAREA0: -242,-92,12810,7836; ORIGINALSYMBOLORIGIN: (0,0); COMPONENTNAME: TP_TP.Normal_package; ID: Q4-G; MAKER: MAC8; COMP: PRT_44; INSTANCENAME: INS4672
TP15 = TP: PARTNAME: HK-2_M8; UPDATEUSER: t5459927; UPDATETIME: 16:40:05; SAVECOUNT: 1; SAVEAREA0: -242,-92,12810,7836; ORIGINALSYMBOLORIGIN: (0,0); COMPONENTNAME: TP_TP.Normal_package; ID: SW; MAKER: MAC8; COMP: PRT_44; INSTANCENAME: INS4696
TP38 = TP: PARTNAME: HK-2_M8; UPDATEUSER: t5459927; UPDATETIME: 16:40:05; SAVECOUNT: 1; SAVEAREA0: -242,-92,12810,7836; ORIGINALSYMBOLORIGIN: (0,0); COMPONENTNAME: TP_TP.Normal_package; ID: OUTA1; MAKER: MAC8; COMP: PRT_44; INSTANCENAME: INS4712
TP39 = TP: PARTNAME: HK-2_M8; UPDATEUSER: t5459927; UPDATETIME: 16:40:05; SAVECOUNT: 1; SAVEAREA0: -242,-92,12810,7836; ORIGINALSYMBOLORIGIN: (0,0); COMPONENTNAME: TP_TP.Normal_package; ID: OUTB1; MAKER: MAC8; COMP: PRT_44; INSTANCENAME: INS4704
U?#4 = WAKU_DEF100: PLOTTIME: HH:MM; SAVEAREA0: 168739,-66042,466246,90057; TIME: 14:30:25; UPDATEUSER: t5459927; UPDATETIME: 15:16:57; SAVECOUNT: 5; OriginalSymbolOrigin: (10160,284480)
